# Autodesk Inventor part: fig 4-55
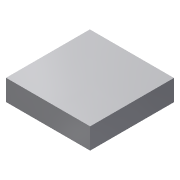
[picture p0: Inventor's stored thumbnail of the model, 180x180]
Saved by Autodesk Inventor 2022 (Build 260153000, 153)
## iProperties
Created: 2010-02
Part Number: fig 4-55
Document SubType Name: Modeling
Designer: CADSoft
Density: 1 g/cm^3
Material: Generic
Appearance: Default
Author: CADSoft
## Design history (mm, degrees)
sketch "Sketch1"
  geometry: L1 (-20.026, 19.961)-(0, 19.961); L2 (0, 19.961)-(0, 0); L3 (0, 0)-(-20.026, 0); L4 (-20.026, 0)-(-20.026, 19.961)
  constraints: 8 end point
extrude "Extrusion1" new body sketch "Sketch1" distance "d0" = 5; taper "d1" = 0 deg
body "Solid1"
